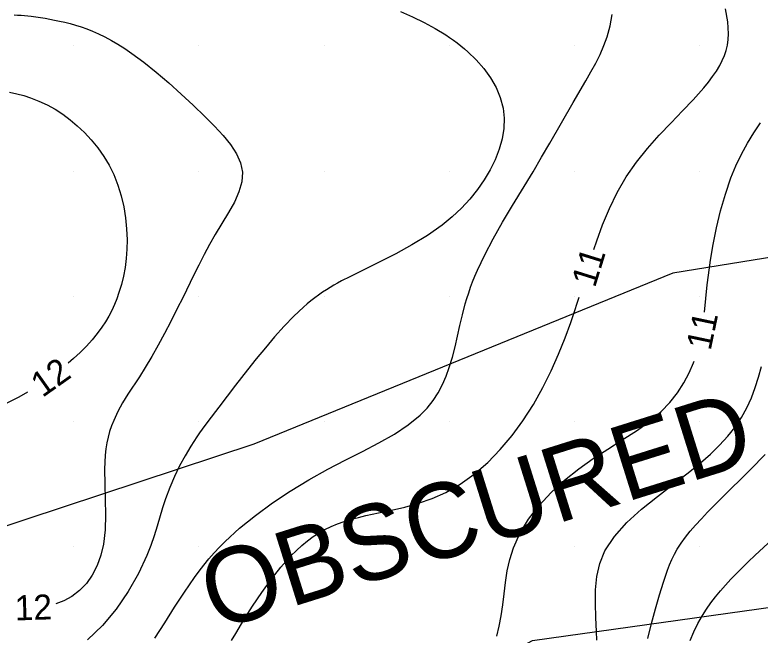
# Model space of a CAD drawing. Extents: x 2602990 to 2605851, y 618069 to 619180.
# Drawn here: x 2603415.3 to 2603474.8, y 618363 to 618412.5 of the extents above; entities that cross this region are included whole.
import ezdxf

# ---------------------------------------------------------------- set-up
doc = ezdxf.new("R2010")
doc.units = 0
for name, color, linetype in [('DTM Contours Major', 7, 'Continuous'), ('DTM Contours Major Text', 7, 'Continuous'), ('DTM Contours Minor', 7, 'Continuous'), ('DTM Contours Minor Text', 7, 'Continuous'), ('Exist DTM Crownline', 7, 'Continuous'), ('Exist DTM QL2 LIDAR Elevation Point', 7, 'Continuous'), ('Exist Roads EOP', 7, 'Continuous'), ('PH Exist DTM Obscure Area', 7, 'Continuous'), ('PH Exist DTM Obscure Area Text', 7, 'Continuous')]:
    doc.layers.add(name, color=color, linetype=linetype)

msp = doc.modelspace()

# ---------------------------------------------------------------- linework, layer by layer
at = {"layer": 'DTM Contours Major'}
for points in [[(2603414.867, 618406.31), (2603415.444, 618406.189), (2603416.001, 618406.041), (2603416.541, 618405.868), (2603417.213, 618405.605), (2603417.866, 618405.297), (2603418.498, 618404.946), (2603419.11, 618404.551), (2603419.701, 618404.114), (2603420.272, 618403.635), (2603420.851, 618403.085), (2603421.4, 618402.492), (2603421.915, 618401.858), (2603422.387, 618401.185), (2603422.813, 618400.474), (2603423.185, 618399.728), (2603423.517, 618398.897), (2603423.785, 618398.038), (2603423.989, 618397.161), (2603424.133, 618396.273), (2603424.22, 618395.386), (2603424.251, 618394.508), (2603424.235, 618393.764), (2603424.181, 618393.035), (2603424.09, 618392.324), (2603423.962, 618391.631), (2603423.801, 618390.957), (2603423.605, 618390.305), (2603423.433, 618389.821), (2603423.241, 618389.348), (2603423.026, 618388.886), (2603422.788, 618388.432), (2603422.525, 618387.984), (2603422.234, 618387.542), (2603421.864, 618387.037), (2603421.454, 618386.535), (2603421.004, 618386.035), (2603420.513, 618385.537), (2603419.979, 618385.038), (2603419.558, 618384.675)], [(2603416.299, 618382.365), (2603415.613, 618381.959), (2603414.211, 618381.271)]]:
    msp.add_lwpolyline(points, dxfattribs=at)
at = {"layer": 'DTM Contours Minor'}
for points in [[(2603415.224, 618412.478), (2603415.507, 618412.468), (2603415.782, 618412.453), (2603416.32, 618412.407), (2603416.587, 618412.377), (2603416.955, 618412.331), (2603417.326, 618412.277), (2603417.702, 618412.215), (2603418.083, 618412.146), (2603418.47, 618412.07), (2603418.866, 618411.985), (2603419.279, 618411.89), (2603419.702, 618411.784), (2603420.135, 618411.663), (2603420.578, 618411.524), (2603421.031, 618411.365), (2603421.494, 618411.182), (2603421.984, 618410.965), (2603422.487, 618410.718), (2603423.001, 618410.44), (2603423.529, 618410.13), (2603424.07, 618409.786), (2603424.626, 618409.408), (2603425.592, 618408.694), (2603426.584, 618407.9), (2603427.584, 618407.049), (2603428.576, 618406.161), (2603429.543, 618405.26), (2603430.469, 618404.366), (2603431.232, 618403.602), (2603431.924, 618402.855), (2603432.519, 618402.119), (2603432.991, 618401.39), (2603433.315, 618400.662), (2603433.465, 618399.928), (2603433.418, 618399.148), (2603433.191, 618398.353), (2603432.825, 618397.54), (2603432.361, 618396.703), (2603431.3, 618394.947), (2603430.85, 618394.154), (2603430.413, 618393.34), (2603429.986, 618392.508), (2603429.565, 618391.663), (2603428.724, 618389.947), (2603428.243, 618388.975), (2603427.754, 618388.007), (2603427.256, 618387.052), (2603426.749, 618386.115), (2603426.232, 618385.205), (2603425.705, 618384.329), (2603425.237, 618383.594), (2603424.323, 618382.185), (2603423.901, 618381.495), (2603423.518, 618380.804), (2603423.185, 618380.104), (2603423.012, 618379.67), (2603422.863, 618379.227), (2603422.736, 618378.773), (2603422.633, 618378.306), (2603422.553, 618377.823), (2603422.497, 618377.322), (2603422.45, 618376.201), (2603422.467, 618375.018), (2603422.508, 618373.799), (2603422.531, 618372.574), (2603422.496, 618371.372), (2603422.361, 618370.219), (2603422.153, 618369.334), (2603421.855, 618368.51), (2603421.471, 618367.759), (2603421.005, 618367.089), (2603420.462, 618366.511), (2603419.844, 618366.035), (2603419.209, 618365.69), (2603418.556, 618365.449)], [(2603446.088, 618412.742), (2603447.049, 618412.324), (2603447.977, 618411.876), (2603448.867, 618411.397), (2603449.711, 618410.884), (2603450.025, 618410.676), (2603450.331, 618410.463), (2603450.63, 618410.243), (2603450.923, 618410.015), (2603451.208, 618409.781), (2603451.486, 618409.538), (2603452.149, 618408.896), (2603452.756, 618408.204), (2603453.29, 618407.467), (2603453.734, 618406.69), (2603454.074, 618405.877), (2603454.291, 618405.033), (2603454.372, 618404.229), (2603454.342, 618403.41), (2603454.209, 618402.581), (2603453.98, 618401.749), (2603453.662, 618400.921), (2603453.264, 618400.103), (2603452.794, 618399.306), (2603452.254, 618398.529), (2603451.645, 618397.776), (2603450.97, 618397.052), (2603450.23, 618396.36), (2603449.427, 618395.704), (2603448.251, 618394.877), (2603447.001, 618394.117), (2603445.718, 618393.414), (2603444.439, 618392.762), (2603442.049, 618391.578), (2603441.389, 618391.235), (2603441.074, 618391.064), (2603440.769, 618390.892), (2603440.472, 618390.717), (2603440.183, 618390.538), (2603439.864, 618390.329), (2603439.551, 618390.112), (2603439.245, 618389.886), (2603438.943, 618389.65), (2603438.644, 618389.403), (2603438.345, 618389.144), (2603437.574, 618388.417), (2603436.806, 618387.622), (2603436.046, 618386.776), (2603435.301, 618385.901), (2603434.576, 618385.015), (2603433.877, 618384.138), (2603432.917, 618382.908), (2603431.581, 618381.165), (2603430.705, 618380.007), (2603430.261, 618379.405), (2603430.043, 618379.098), (2603429.828, 618378.786), (2603429.35, 618378.052), (2603428.889, 618377.28), (2603428.452, 618376.471), (2603428.042, 618375.627), (2603427.664, 618374.748), (2603427.325, 618373.837), (2603427.096, 618373.129), (2603426.655, 618371.66), (2603426.418, 618370.897), (2603426.151, 618370.116), (2603425.841, 618369.317), (2603425.168, 618367.881), (2603424.34, 618366.439), (2603423.372, 618365.04), (2603422.281, 618363.735), (2603421.085, 618362.576)], [(2603426.466, 618362.705), (2603427.264, 618363.944), (2603428.049, 618365.181), (2603428.835, 618366.391), (2603429.635, 618367.551), (2603430.012, 618368.061), (2603430.397, 618368.558), (2603430.794, 618369.042), (2603431.208, 618369.517), (2603431.639, 618369.984), (2603432.093, 618370.444), (2603433.242, 618371.498), (2603434.506, 618372.522), (2603435.864, 618373.511), (2603437.294, 618374.458), (2603438.776, 618375.358), (2603440.288, 618376.204), (2603441.688, 618376.934), (2603443.063, 618377.633), (2603444.38, 618378.32), (2603445.609, 618379.016), (2603446.717, 618379.74), (2603447.671, 618380.512), (2603448.226, 618381.081), (2603448.703, 618381.681), (2603449.109, 618382.308), (2603449.454, 618382.96), (2603449.747, 618383.635), (2603449.997, 618384.33), (2603450.242, 618385.142), (2603450.456, 618385.974), (2603450.653, 618386.821), (2603450.847, 618387.678), (2603451.051, 618388.541), (2603451.278, 618389.408), (2603451.407, 618389.847), (2603451.546, 618390.287), (2603451.697, 618390.729), (2603451.862, 618391.176), (2603452.042, 618391.627), (2603452.237, 618392.086), (2603452.826, 618393.325), (2603453.508, 618394.61), (2603454.259, 618395.927), (2603455.055, 618397.266), (2603456.684, 618399.96), (2603457.366, 618401.111), (2603458.027, 618402.245), (2603459.889, 618405.484), (2603460.901, 618407.223), (2603461.311, 618407.936), (2603461.695, 618408.636), (2603462.045, 618409.33), (2603462.353, 618410.025), (2603462.611, 618410.728), (2603462.853, 618411.617), (2603463.014, 618412.519)], [(2603461.556, 618393.762), (2603461.779, 618394.446), (2603462.246, 618395.731), (2603462.784, 618397.027), (2603463.409, 618398.308), (2603464.136, 618399.554), (2603464.95, 618400.718), (2603465.841, 618401.825), (2603466.774, 618402.877), (2603467.714, 618403.874), (2603468.627, 618404.817), (2603469.478, 618405.708), (2603469.916, 618406.184), (2603470.322, 618406.648), (2603470.695, 618407.102), (2603471.033, 618407.551), (2603471.336, 618407.997), (2603471.602, 618408.445), (2603471.803, 618408.839), (2603471.972, 618409.24), (2603472.109, 618409.649), (2603472.211, 618410.072), (2603472.277, 618410.509), (2603472.305, 618410.964), (2603472.246, 618411.932), (2603472.05, 618412.961)], [(2603470.375, 618388.746), (2603470.609, 618390.916), (2603470.706, 618391.7), (2603470.873, 618392.887), (2603471.085, 618394.157), (2603471.348, 618395.481), (2603471.667, 618396.829), (2603472.05, 618398.17), (2603472.501, 618399.475), (2603472.896, 618400.432), (2603473.333, 618401.351), (2603473.808, 618402.23), (2603474.32, 618403.069), (2603474.865, 618403.867)], [(2603432.593, 618362.523), (2603432.933, 618363.102), (2603433.581, 618364.173), (2603434.276, 618365.268), (2603435.008, 618366.357), (2603435.769, 618367.41), (2603436.551, 618368.396), (2603437.344, 618369.287), (2603437.782, 618369.726), (2603438.224, 618370.128), (2603438.67, 618370.494), (2603439.124, 618370.827), (2603439.588, 618371.126), (2603440.063, 618371.393), (2603440.562, 618371.634), (2603441.078, 618371.848), (2603441.611, 618372.038), (2603442.164, 618372.208), (2603442.739, 618372.363), (2603443.338, 618372.506), (2603444.334, 618372.719), (2603445.377, 618372.938), (2603446.453, 618373.186), (2603447.544, 618373.486), (2603448.637, 618373.864), (2603449.714, 618374.342), (2603450.877, 618375.012), (2603451.996, 618375.819), (2603453.063, 618376.747), (2603454.071, 618377.777), (2603455.013, 618378.895), (2603455.883, 618380.081), (2603456.713, 618381.385), (2603457.46, 618382.723), (2603458.127, 618384.07), (2603458.72, 618385.402), (2603459.242, 618386.695), (2603459.698, 618387.924), (2603459.952, 618388.651), (2603460.301, 618389.702), (2603460.375, 618389.94)], [(2603453.794, 618362.887), (2603453.992, 618363.678), (2603454.151, 618364.504), (2603454.273, 618365.375), (2603454.375, 618366.267), (2603454.484, 618367.174), (2603454.626, 618368.089), (2603454.827, 618369.006), (2603455.115, 618369.919), (2603455.64, 618371.076), (2603456.332, 618372.206), (2603457.168, 618373.297), (2603458.128, 618374.34), (2603459.192, 618375.327), (2603460.34, 618376.246), (2603461.487, 618377.054), (2603462.658, 618377.815), (2603463.82, 618378.549), (2603464.94, 618379.279), (2603465.984, 618380.027), (2603466.92, 618380.813), (2603467.623, 618381.54), (2603468.227, 618382.303), (2603468.738, 618383.091), (2603469.163, 618383.895), (2603469.509, 618384.704), (2603469.556, 618384.842)], [(2603461.787, 618362.546), (2603461.764, 618363.252), (2603461.714, 618364.371), (2603461.676, 618365.479), (2603461.69, 618366.571), (2603461.796, 618367.64), (2603462.031, 618368.677), (2603462.435, 618369.677), (2603463.193, 618370.842), (2603464.192, 618371.951), (2603465.363, 618373.013), (2603466.638, 618374.04), (2603467.948, 618375.042), (2603469.223, 618376.028), (2603470.069, 618376.721), (2603470.858, 618377.417), (2603471.586, 618378.121), (2603472.246, 618378.838), (2603472.835, 618379.574), (2603473.347, 618380.333), (2603473.773, 618381.106), (2603474.133, 618381.904), (2603474.44, 618382.724), (2603474.706, 618383.563), (2603474.944, 618384.419)], [(2603465.859, 618362.678), (2603466.154, 618363.887), (2603466.462, 618365.055), (2603466.778, 618366.165), (2603467.098, 618367.198), (2603467.257, 618367.678), (2603467.42, 618368.137), (2603467.592, 618368.579), (2603467.776, 618369.006), (2603467.979, 618369.419), (2603468.203, 618369.823), (2603468.512, 618370.306), (2603468.861, 618370.784), (2603469.248, 618371.263), (2603469.673, 618371.75), (2603470.135, 618372.25), (2603470.634, 618372.771), (2603471.708, 618373.858), (2603474.059, 618376.194), (2603475.231, 618377.371)], [(2603469.237, 618362.522), (2603469.535, 618363.211), (2603469.862, 618363.876), (2603470.219, 618364.515), (2603470.545, 618365.032), (2603470.893, 618365.532), (2603471.263, 618366.017), (2603471.653, 618366.492), (2603472.061, 618366.958), (2603472.488, 618367.419), (2603472.942, 618367.889), (2603473.414, 618368.36), (2603473.904, 618368.833), (2603474.411, 618369.312), (2603475.483, 618370.298)]]:
    msp.add_lwpolyline(points, dxfattribs=at)
at = {"layer": 'Exist DTM Crownline'}
msp.add_spline([(2603233.488, 618380.754), (2603285.185, 618400.095), (2603335.457, 618418.629), (2603390.812, 618439.069), (2603440.087, 618457.325), (2603493.996, 618477.231), (2603542.655, 618495.301), (2603600.808, 618516.867), (2603653.659, 618536.362), (2603706.222, 618555.742), (2603764.811, 618577.593), (2603823.52, 618599.847), (2603878.564, 618620.56), (2603937.951, 618643.078), (2603997.369, 618665.789), (2604036.209, 618680.665), (2604055.311, 618688.017)], degree=3, dxfattribs=at)
at = {"layer": 'Exist DTM QL2 LIDAR Elevation Point'}
for p, q in [((2603420, 618410), (2603420, 618410)), ((2603430, 618410), (2603430, 618410)), ((2603440, 618410), (2603440, 618410)), ((2603450, 618410), (2603450, 618410)), ((2603460, 618410), (2603460, 618410)), ((2603470, 618410), (2603470, 618410)), ((2603420, 618400), (2603420, 618400)), ((2603430, 618400), (2603430, 618400)), ((2603440, 618400), (2603440, 618400)), ((2603450, 618400), (2603450, 618400)), ((2603460, 618400), (2603460, 618400)), ((2603470, 618400), (2603470, 618400)), ((2603420, 618390), (2603420, 618390)), ((2603430, 618390), (2603430, 618390)), ((2603440, 618390), (2603440, 618390)), ((2603450, 618390), (2603450, 618390)), ((2603460, 618390), (2603460, 618390)), ((2603470, 618390), (2603470, 618390)), ((2603420, 618380), (2603420, 618380)), ((2603430, 618380), (2603430, 618380)), ((2603440, 618380), (2603440, 618380)), ((2603450, 618380), (2603450, 618380)), ((2603460, 618380), (2603460, 618380)), ((2603470, 618380), (2603470, 618380)), ((2603420, 618370), (2603420, 618370)), ((2603430, 618370), (2603430, 618370)), ((2603440, 618370), (2603440, 618370)), ((2603450, 618370), (2603450, 618370)), ((2603460, 618370), (2603460, 618370)), ((2603470, 618370), (2603470, 618370))]:
    msp.add_line(p, q, dxfattribs=at)
at = {"layer": 'Exist Roads EOP'}
for points in [[(2603230.17, 618389.98), (2603282.929, 618409.597), (2603332.773, 618427.868), (2603388.167, 618448.413), (2603437.203, 618466.721), (2603490.778, 618486.527), (2603539.039, 618504.558), (2603597.451, 618526.156), (2603651.053, 618545.972), (2603705.208, 618566.084), (2603762.02, 618587.183), (2603820.334, 618609.162), (2603876.341, 618629.99), (2603934.909, 618652.28), (2603996.409, 618675.568), (2604033.216, 618689.957), (2604052.01, 618697.199)], [(2604034.633, 618668.486), (2603984.89, 618650.123), (2603936.767, 618631.654), (2603888.195, 618613.335), (2603837.766, 618594.258), (2603782.918, 618573.705), (2603731.939, 618554.39), (2603671.126, 618532.171), (2603621.822, 618514.106), (2603561.545, 618491.877), (2603506.421, 618471.293), (2603452.163, 618451.33), (2603398.364, 618431.316), (2603341.431, 618410.355), (2603281.65, 618388.199), (2603223.033, 618366.475), (2603185.717, 618352.612)]]:
    msp.add_spline(points, degree=3, dxfattribs=at)
at = {"layer": 'PH Exist DTM Obscure Area'}
msp.add_lwpolyline([(2603403.954, 618347.019), (2603416.176, 618350.3), (2603425.046, 618351.063), (2603435.654, 618353.776), (2603446.032, 618356.835), (2603456.654, 618362.542), (2603477.396, 618365.436), (2603486.975, 618369.881), (2603496.095, 618374.674), (2603501.994, 618380.058), (2603502.037, 618389.04), (2603497.447, 618392.401), (2603487.095, 618394.985), (2603467.85, 618391.853), (2603434.389, 618378.195), (2603391.714, 618364.121)], dxfattribs=at)

# ---------------------------------------------------------------- texts
at = {"layer": 'DTM Contours Major Text'}
msp.add_text('12', height=2, rotation=35.32934, dxfattribs=at).set_placement((2603417.495, 618381.884))
at = {"layer": 'DTM Contours Minor Text'}
for s, rotation, p in [('11', 72.83058, (2603461.632, 618390.64)), ('11', 78.1426, (2603470.872, 618385.622)), ('12', 1.86224, (2603415.317, 618364.127))]:
    msp.add_text(s, height=2, rotation=rotation, dxfattribs=at).set_placement(p)
at = {"layer": 'PH Exist DTM Obscure Area Text'}
msp.add_text('OBSCURED', height=6, rotation=17.42237, dxfattribs=at).set_placement((2603431.309, 618363.277))

doc.saveas('drawing.dxf')
